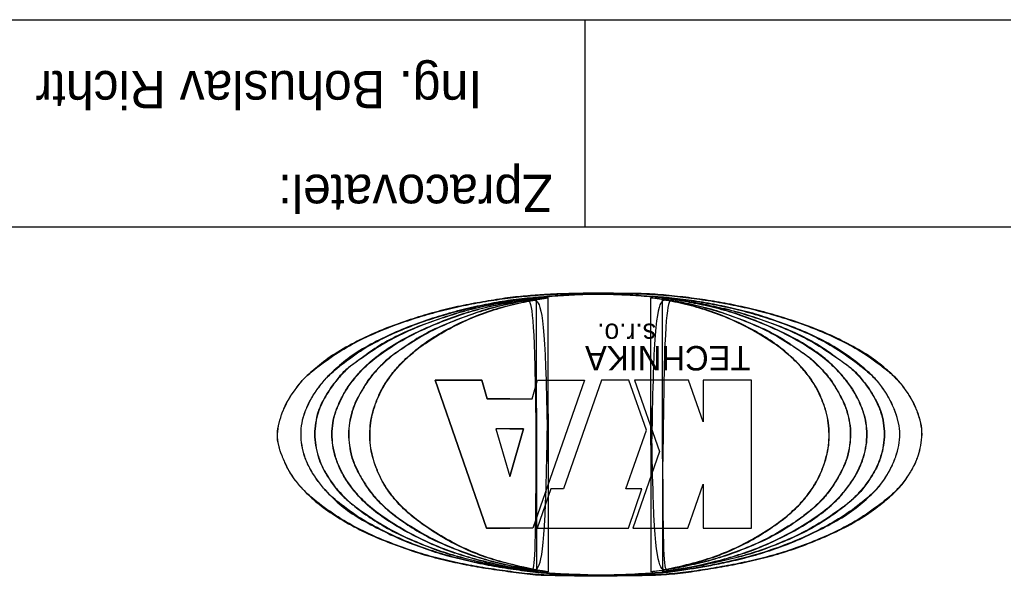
# Model space of a CAD drawing. Extents: x -728452 to -728347, y -1073107 to -1072959.
# Drawn here: x -728436.11 to -728412.4, y -1073023.46 to -1073009.8 of the extents above; entities that cross this region are included whole.
import ezdxf

# ---------------------------------------------------------------- set-up
doc = ezdxf.new("R2010")
doc.units = 0
doc.layers.add('Dočasný_nad_1_rok', color=7, linetype='Continuous')
doc.layers.add('Dočasný_nad_1_rok_PUPFL', color=7, linetype='Continuous')

msp = doc.modelspace()

# ---------------------------------------------------------------- linework, layer by layer
at = {"layer": 'Dočasný_nad_1_rok'}
msp.add_line((-728424.294, -1073022.056), (-728424.851, -1073022.056), dxfattribs=at)
for points in [[(-728424.294, -1073018.942), (-728424.836, -1073018.942), (-728424.968, -1073018.486), (-728426.094, -1073018.487), (-728424.851, -1073022.056), (-728424.294, -1073022.056)], [(-728424.851, -1073022.056), (-728426.094, -1073018.487), (-728424.968, -1073018.486), (-728424.836, -1073018.942), (-728424.294, -1073018.942)], [(-728424.294, -1073018.942), (-728423.753, -1073018.942), (-728423.621, -1073018.486), (-728422.495, -1073018.487), (-728423.738, -1073022.056), (-728424.294, -1073022.056)], [(-728424.294, -1073018.942), (-728423.753, -1073018.942), (-728423.621, -1073018.486), (-728422.495, -1073018.487), (-728423.738, -1073022.056), (-728424.294, -1073022.056)], [(-728421.435, -1073022.056), (-728421.107, -1073021.113), (-728421.495, -1073021.113), (-728421.001, -1073019.693), (-728421.421, -1073018.486), (-728422.085, -1073018.486), (-728423, -1073021.113), (-728423.302, -1073021.113), (-728423.63, -1073022.056), (-728421.435, -1073022.056)], [(-728421.435, -1073022.056), (-728421.107, -1073021.113), (-728421.495, -1073021.113), (-728421.001, -1073019.693), (-728421.421, -1073018.486), (-728422.085, -1073018.486), (-728423, -1073021.113), (-728423.302, -1073021.113), (-728423.63, -1073022.056), (-728421.435, -1073022.056)], [(-728418.466, -1073022.056), (-728418.466, -1073018.486), (-728419.635, -1073018.486), (-728419.635, -1073019.492), (-728419.985, -1073018.486), (-728421.285, -1073018.486), (-728420.685, -1073020.209), (-728421.328, -1073022.056), (-728420.003, -1073022.056), (-728419.635, -1073020.998), (-728419.635, -1073022.056), (-728418.466, -1073022.056)], [(-728418.466, -1073022.056), (-728418.466, -1073018.486), (-728419.635, -1073018.486), (-728419.635, -1073019.492), (-728419.985, -1073018.486), (-728421.285, -1073018.486), (-728420.685, -1073020.209), (-728421.328, -1073022.056), (-728420.003, -1073022.056), (-728419.635, -1073020.998), (-728419.635, -1073022.056), (-728418.466, -1073022.056)], [(-728424.294, -1073019.665), (-728424.626, -1073019.665), (-728424.294, -1073020.813)], [(-728424.294, -1073019.665), (-728424.626, -1073019.665), (-728424.294, -1073020.813)], [(-728424.294, -1073019.665), (-728423.962, -1073019.665), (-728424.294, -1073020.813)], [(-728424.294, -1073020.813), (-728423.962, -1073019.665), (-728424.294, -1073019.665)]]:
    msp.add_lwpolyline(points, dxfattribs=at)
for points in [[(-728423.358, -1073016.421), (-728423.485, -1073016.428), (-728423.79, -1073016.45), (-728424.276, -1073016.491), (-728424.81, -1073016.579), (-728425.348, -1073016.67), (-728425.885, -1073016.792), (-728426.423, -1073016.94), (-728426.96, -1073017.117), (-728427.498, -1073017.323), (-728428.038, -1073017.576), (-728428.59, -1073017.889), (-728428.983, -1073018.211), (-728429.3, -1073018.476), (-728429.469, -1073018.716), (-728429.656, -1073018.975), (-728429.776, -1073019.251), (-728429.866, -1073019.519), (-728429.918, -1073019.791), (-728429.881, -1073020.068), (-728429.779, -1073020.334), (-728429.665, -1073020.608), (-728429.497, -1073020.882), (-728429.302, -1073021.107), (-728429, -1073021.403), (-728428.589, -1073021.714), (-728428.042, -1073022.034), (-728427.504, -1073022.292), (-728426.96, -1073022.493), (-728426.428, -1073022.686), (-728425.885, -1073022.82), (-728425.349, -1073022.944), (-728424.808, -1073023.035), (-728424.271, -1073023.105), (-728423.738, -1073023.188), (-728423.202, -1073023.194), (-728422.666, -1073023.205), (-728422.309, -1073023.208), (-728422.13, -1073023.209)], [(-728422.13, -1073023.209), (-728421.524, -1073023.201), (-728421.057, -1073023.194), (-728420.521, -1073023.172), (-728419.985, -1073023.116), (-728419.45, -1073023.032), (-728418.912, -1073022.939), (-728418.377, -1073022.824), (-728417.841, -1073022.684), (-728417.303, -1073022.509), (-728416.767, -1073022.295), (-728416.234, -1073022.049), (-728415.697, -1073021.731), (-728415.161, -1073021.327), (-728414.953, -1073021.133), (-728414.734, -1073020.864), (-728414.572, -1073020.597), (-728414.451, -1073020.328), (-728414.386, -1073020.061), (-728414.356, -1073019.793), (-728414.384, -1073019.529), (-728414.465, -1073019.258), (-728414.586, -1073018.988), (-728414.754, -1073018.722), (-728414.97, -1073018.453), (-728415.161, -1073018.274), (-728415.697, -1073017.868), (-728416.233, -1073017.565), (-728416.763, -1073017.318), (-728417.305, -1073017.113), (-728417.843, -1073016.939), (-728418.376, -1073016.793), (-728418.909, -1073016.675), (-728419.447, -1073016.577), (-728419.985, -1073016.501), (-728420.523, -1073016.442), (-728421.054, -1073016.406), (-728421.594, -1073016.4), (-728422.13, -1073016.391), (-728422.666, -1073016.4), (-728423.203, -1073016.414), (-728423.739, -1073016.447), (-728424.272, -1073016.498), (-728424.81, -1073016.579), (-728425.345, -1073016.674), (-728425.881, -1073016.795), (-728426.419, -1073016.944), (-728426.955, -1073017.12), (-728427.491, -1073017.328), (-728428.024, -1073017.577), (-728428.564, -1073017.893), (-728429.103, -1073018.311), (-728429.263, -1073018.454), (-728429.473, -1073018.72), (-728429.65, -1073018.987), (-728429.774, -1073019.257), (-728429.861, -1073019.524), (-728429.904, -1073019.793), (-728429.872, -1073020.06), (-728429.78, -1073020.329), (-728429.659, -1073020.603), (-728429.499, -1073020.864), (-728429.272, -1073021.133), (-728429.106, -1073021.296), (-728428.565, -1073021.715), (-728428.029, -1073022.032), (-728427.496, -1073022.286), (-728426.958, -1073022.493), (-728426.419, -1073022.678), (-728425.886, -1073022.818), (-728425.346, -1073022.939), (-728424.807, -1073023.031), (-728424.268, -1073023.107), (-728423.737, -1073023.175), (-728423.202, -1073023.194), (-728422.667, -1073023.204), (-728422.13, -1073023.209), (-728422.13, -1073023.209), (-728422.13, -1073023.209)], [(-728422.13, -1073023.194), (-728422.309, -1073023.187), (-728422.666, -1073023.173), (-728423.204, -1073023.167), (-728423.739, -1073023.109), (-728424.275, -1073023.04), (-728424.813, -1073022.951), (-728425.348, -1073022.833), (-728425.889, -1073022.704), (-728426.424, -1073022.522), (-728426.965, -1073022.316), (-728427.499, -1073022.051), (-728428.056, -1073021.752), (-728428.468, -1073021.424), (-728428.773, -1073021.118), (-728428.965, -1073020.876), (-728429.13, -1073020.605), (-728429.252, -1073020.336), (-728429.316, -1073020.062), (-728429.34, -1073019.792), (-728429.319, -1073019.519), (-728429.238, -1073019.25), (-728429.118, -1073018.979), (-728428.946, -1073018.711), (-728428.764, -1073018.473), (-728428.455, -1073018.183), (-728428.056, -1073017.853), (-728427.503, -1073017.541), (-728426.962, -1073017.291), (-728426.424, -1073017.082), (-728425.885, -1073016.913), (-728425.349, -1073016.764), (-728424.811, -1073016.653), (-728424.275, -1073016.555), (-728423.737, -1073016.502), (-728423.202, -1073016.456), (-728422.666, -1073016.422), (-728422.13, -1073016.404), (-728421.593, -1073016.424), (-728421.057, -1073016.463), (-728420.52, -1073016.492), (-728419.983, -1073016.556), (-728419.446, -1073016.643), (-728418.909, -1073016.756), (-728418.37, -1073016.889), (-728417.837, -1073017.074), (-728417.295, -1073017.268), (-728416.752, -1073017.514), (-728416.213, -1073017.841), (-728415.79, -1073018.162), (-728415.467, -1073018.457), (-728415.274, -1073018.709), (-728415.114, -1073018.981), (-728414.994, -1073019.251), (-728414.919, -1073019.521), (-728414.872, -1073019.792), (-728414.913, -1073020.064), (-728414.983, -1073020.335), (-728415.096, -1073020.606), (-728415.255, -1073020.875), (-728415.448, -1073021.139), (-728415.783, -1073021.437), (-728416.206, -1073021.773), (-728416.761, -1073022.069), (-728417.295, -1073022.329), (-728417.834, -1073022.538), (-728418.372, -1073022.71), (-728418.91, -1073022.848), (-728419.368, -1073022.939), (-728419.726, -1073023.004), (-728420.083, -1073023.062), (-728420.52, -1073023.126), (-728421.057, -1073023.16), (-728421.593, -1073023.182), (-728421.951, -1073023.19), (-728422.13, -1073023.194)], [(-728422.13, -1073023.194), (-728421.593, -1073023.18), (-728421.057, -1073023.158), (-728420.522, -1073023.119), (-728419.986, -1073023.046), (-728419.744, -1073023.006), (-728419.45, -1073022.953), (-728418.913, -1073022.843), (-728418.377, -1073022.706), (-728417.84, -1073022.534), (-728417.304, -1073022.324), (-728416.767, -1073022.068), (-728416.234, -1073021.768), (-728415.698, -1073021.358), (-728415.459, -1073021.133), (-728415.254, -1073020.864), (-728415.1, -1073020.598), (-728414.987, -1073020.328), (-728414.917, -1073020.061), (-728414.886, -1073019.792), (-728414.923, -1073019.525), (-728414.999, -1073019.258), (-728415.116, -1073018.989), (-728415.274, -1073018.721), (-728415.484, -1073018.452), (-728415.698, -1073018.25), (-728416.233, -1073017.841), (-728416.767, -1073017.52), (-728417.303, -1073017.273), (-728417.839, -1073017.074), (-728418.376, -1073016.896), (-728418.912, -1073016.759), (-728419.448, -1073016.647), (-728419.985, -1073016.559), (-728420.521, -1073016.498), (-728421.057, -1073016.461), (-728421.594, -1073016.427), (-728422.13, -1073016.41), (-728422.665, -1073016.424), (-728423.203, -1073016.458), (-728423.736, -1073016.503), (-728424.272, -1073016.562), (-728424.809, -1073016.655), (-728425.345, -1073016.77), (-728425.881, -1073016.915), (-728426.419, -1073017.087), (-728426.955, -1073017.294), (-728427.49, -1073017.544), (-728428.028, -1073017.857), (-728428.563, -1073018.286), (-728428.735, -1073018.453), (-728428.948, -1073018.722), (-728429.114, -1073018.988), (-728429.234, -1073019.257), (-728429.31, -1073019.524), (-728429.333, -1073019.79), (-728429.31, -1073020.06), (-728429.246, -1073020.327), (-728429.128, -1073020.596), (-728428.965, -1073020.864), (-728428.752, -1073021.133), (-728428.564, -1073021.324), (-728428.028, -1073021.747), (-728427.491, -1073022.052), (-728426.955, -1073022.31), (-728426.419, -1073022.52), (-728425.882, -1073022.697), (-728425.346, -1073022.832), (-728424.81, -1073022.947), (-728424.273, -1073023.037), (-728423.737, -1073023.107), (-728423.203, -1073023.159), (-728422.667, -1073023.175), (-728422.13, -1073023.194), (-728422.13, -1073023.194), (-728422.13, -1073023.194)], [(-728423.648, -1073016.51), (-728423.751, -1073016.519), (-728423.961, -1073016.536), (-728424.35, -1073016.596), (-728424.815, -1073016.691), (-728425.357, -1073016.807), (-728425.891, -1073016.978), (-728426.43, -1073017.164), (-728426.97, -1073017.397), (-728427.517, -1073017.69), (-728427.898, -1073017.991), (-728428.237, -1073018.214), (-728428.437, -1073018.44), (-728428.642, -1073018.713), (-728428.801, -1073018.982), (-728428.924, -1073019.247), (-728428.979, -1073019.522), (-728429.009, -1073019.792), (-728428.98, -1073020.063), (-728428.918, -1073020.335), (-728428.813, -1073020.61), (-728428.647, -1073020.872), (-728428.455, -1073021.156), (-728428.236, -1073021.366), (-728427.915, -1073021.628), (-728427.512, -1073021.91), (-728426.969, -1073022.216), (-728426.426, -1073022.444), (-728425.891, -1073022.648), (-728425.351, -1073022.793), (-728424.81, -1073022.914), (-728424.275, -1073023.021), (-728423.887, -1073023.09), (-728423.678, -1073023.102), (-728423.65, -1073023.104)], [(-728423.648, -1073016.51), (-728423.956, -1073016.539), (-728424.277, -1073016.586), (-728424.813, -1073016.691), (-728425.352, -1073016.815), (-728425.889, -1073016.979), (-728426.423, -1073017.168), (-728426.956, -1073017.4), (-728427.494, -1073017.698), (-728428.033, -1073018.079), (-728428.178, -1073018.181), (-728428.441, -1073018.452), (-728428.644, -1073018.726), (-728428.799, -1073018.989), (-728428.914, -1073019.254), (-728428.975, -1073019.526), (-728428.999, -1073019.794), (-728428.975, -1073020.057), (-728428.912, -1073020.33), (-728428.807, -1073020.6), (-728428.649, -1073020.865), (-728428.457, -1073021.133), (-728428.184, -1073021.406), (-728428.037, -1073021.527), (-728427.494, -1073021.909), (-728426.953, -1073022.211), (-728426.418, -1073022.443), (-728425.89, -1073022.638), (-728425.342, -1073022.791), (-728424.811, -1073022.912), (-728424.272, -1073023.02), (-728423.734, -1073023.099), (-728423.65, -1073023.104), (-728423.648, -1073016.51), (-728423.65, -1073023.104)], [(-728423.65, -1073023.104), (-728423.843, -1073023.075), (-728424.232, -1073023.017), (-728424.8, -1073022.9), (-728425.353, -1073022.748), (-728425.893, -1073022.569), (-728426.429, -1073022.333), (-728426.97, -1073022.049), (-728427.444, -1073021.74), (-728427.816, -1073021.429), (-728428.064, -1073021.143), (-728428.258, -1073020.877), (-728428.403, -1073020.606), (-728428.506, -1073020.335), (-728428.568, -1073020.063), (-728428.586, -1073019.791), (-728428.567, -1073019.521), (-728428.499, -1073019.25), (-728428.383, -1073018.983), (-728428.242, -1073018.708), (-728428.04, -1073018.443), (-728427.796, -1073018.165), (-728427.436, -1073017.855), (-728426.97, -1073017.551), (-728426.426, -1073017.277), (-728425.887, -1073017.048), (-728425.352, -1073016.857), (-728424.814, -1073016.713), (-728424.328, -1073016.614), (-728423.939, -1073016.55), (-728423.73, -1073016.521), (-728423.648, -1073016.51)], [(-728423.65, -1073023.104), (-728424.229, -1073023.012), (-728424.81, -1073022.891), (-728425.349, -1073022.744), (-728425.887, -1073022.562), (-728426.418, -1073022.331), (-728426.954, -1073022.047), (-728427.491, -1073021.691), (-728427.828, -1073021.402), (-728428.067, -1073021.131), (-728428.256, -1073020.866), (-728428.398, -1073020.601), (-728428.501, -1073020.329), (-728428.562, -1073020.058), (-728428.58, -1073019.793), (-728428.559, -1073019.523), (-728428.493, -1073019.257), (-728428.383, -1073018.99), (-728428.238, -1073018.719), (-728428.044, -1073018.454), (-728427.804, -1073018.186), (-728427.486, -1073017.908), (-728426.955, -1073017.556), (-728426.416, -1073017.28), (-728425.881, -1073017.052), (-728425.345, -1073016.863), (-728424.811, -1073016.718), (-728424.274, -1073016.607), (-728423.893, -1073016.544), (-728423.648, -1073016.51), (-728423.65, -1073023.104), (-728423.648, -1073016.51)], [(-728423.369, -1073016.502), (-728423.492, -1073016.512), (-728423.797, -1073016.539), (-728424.276, -1073016.641), (-728424.817, -1073016.763), (-728425.35, -1073016.948), (-728425.891, -1073017.156), (-728426.44, -1073017.416), (-728426.844, -1073017.702), (-728427.203, -1073017.939), (-728427.44, -1073018.174), (-728427.683, -1073018.436), (-728427.849, -1073018.718), (-728428.003, -1073018.98), (-728428.106, -1073019.25), (-728428.163, -1073019.52), (-728428.193, -1073019.791), (-728428.16, -1073020.062), (-728428.118, -1073020.335), (-728428.007, -1073020.604), (-728427.864, -1073020.871), (-728427.69, -1073021.146), (-728427.463, -1073021.42), (-728427.207, -1073021.648), (-728426.858, -1073021.911), (-728426.436, -1073022.188), (-728425.893, -1073022.454), (-728425.354, -1073022.664), (-728424.818, -1073022.84), (-728424.278, -1073022.963), (-728423.797, -1073023.062), (-728423.492, -1073023.097), (-728423.369, -1073023.111)], [(-728423.369, -1073016.502), (-728423.737, -1073016.54), (-728424.276, -1073016.642), (-728424.807, -1073016.771), (-728425.346, -1073016.95), (-728425.884, -1073017.16), (-728426.417, -1073017.423), (-728426.954, -1073017.774), (-728427.157, -1073017.916), (-728427.449, -1073018.186), (-728427.68, -1073018.452), (-728427.851, -1073018.721), (-728427.998, -1073018.989), (-728428.101, -1073019.257), (-728428.159, -1073019.52), (-728428.182, -1073019.792), (-728428.159, -1073020.062), (-728428.109, -1073020.328), (-728428.006, -1073020.594), (-728427.862, -1073020.867), (-728427.691, -1073021.133), (-728427.467, -1073021.402), (-728427.173, -1073021.67), (-728426.952, -1073021.838), (-728426.418, -1073022.183), (-728425.884, -1073022.449), (-728425.345, -1073022.662), (-728424.813, -1073022.833), (-728424.277, -1073022.961), (-728423.737, -1073023.065), (-728423.369, -1073023.111), (-728423.369, -1073016.502), (-728423.369, -1073023.111)], [(-728423.369, -1073023.111), (-728423.492, -1073023.093), (-728423.796, -1073023.049), (-728424.276, -1073022.931), (-728424.819, -1073022.787), (-728425.36, -1073022.576), (-728425.899, -1073022.298), (-728426.371, -1073021.989), (-728426.758, -1073021.692), (-728427.029, -1073021.412), (-728427.242, -1073021.145), (-728427.403, -1073020.873), (-728427.519, -1073020.602), (-728427.606, -1073020.332), (-728427.662, -1073020.063), (-728427.67, -1073019.792), (-728427.655, -1073019.522), (-728427.603, -1073019.251), (-728427.507, -1073018.985), (-728427.389, -1073018.711), (-728427.219, -1073018.444), (-728427.006, -1073018.173), (-728426.736, -1073017.907), (-728426.368, -1073017.6), (-728425.899, -1073017.308), (-728425.358, -1073017.04), (-728424.82, -1073016.821), (-728424.278, -1073016.67), (-728423.794, -1073016.57), (-728423.492, -1073016.522), (-728423.369, -1073016.502)], [(-728423.369, -1073023.111), (-728423.737, -1073023.053), (-728424.273, -1073022.93), (-728424.811, -1073022.778), (-728425.347, -1073022.57), (-728425.883, -1073022.295), (-728426.419, -1073021.947), (-728426.771, -1073021.667), (-728427.031, -1073021.401), (-728427.242, -1073021.132), (-728427.4, -1073020.866), (-728427.517, -1073020.597), (-728427.602, -1073020.329), (-728427.655, -1073020.06), (-728427.667, -1073019.794), (-728427.649, -1073019.525), (-728427.596, -1073019.256), (-728427.506, -1073018.99), (-728427.385, -1073018.722), (-728427.219, -1073018.453), (-728427.011, -1073018.19), (-728426.741, -1073017.919), (-728426.419, -1073017.653), (-728425.884, -1073017.311), (-728425.348, -1073017.043), (-728424.812, -1073016.83), (-728424.271, -1073016.675), (-728423.738, -1073016.563), (-728423.369, -1073016.502), (-728423.369, -1073023.111), (-728423.369, -1073016.502)], [(-728422.13, -1073023.209), (-728421.928, -1073023.206), (-728421.57, -1073023.2), (-728421.034, -1073023.196), (-728420.52, -1073023.179), (-728419.983, -1073023.121), (-728419.449, -1073023.032), (-728418.911, -1073022.943), (-728418.374, -1073022.827), (-728417.835, -1073022.688), (-728417.297, -1073022.513), (-728416.763, -1073022.297), (-728416.218, -1073022.054), (-728415.678, -1073021.732), (-728415.255, -1073021.416), (-728414.933, -1073021.124), (-728414.735, -1073020.877), (-728414.57, -1073020.605), (-728414.442, -1073020.338), (-728414.384, -1073020.063), (-728414.344, -1073019.795), (-728414.376, -1073019.521), (-728414.462, -1073019.252), (-728414.581, -1073018.978), (-728414.756, -1073018.712), (-728414.944, -1073018.467), (-728415.262, -1073018.181), (-728415.672, -1073017.863), (-728416.221, -1073017.564), (-728416.758, -1073017.311), (-728417.299, -1073017.111), (-728417.837, -1073016.936), (-728418.372, -1073016.788), (-728418.909, -1073016.672), (-728419.445, -1073016.573), (-728419.984, -1073016.498), (-728420.52, -1073016.44), (-728421.056, -1073016.397), (-728421.592, -1073016.404), (-728422.13, -1073016.385), (-728422.666, -1073016.401), (-728423.076, -1073016.407), (-728423.307, -1073016.418), (-728423.358, -1073016.421)], [(-728420.89, -1073016.502), (-728420.767, -1073016.512), (-728420.462, -1073016.539), (-728419.983, -1073016.641), (-728419.442, -1073016.763), (-728418.909, -1073016.948), (-728418.368, -1073017.156), (-728417.819, -1073017.416), (-728417.415, -1073017.702), (-728417.056, -1073017.939), (-728416.819, -1073018.174), (-728416.576, -1073018.436), (-728416.41, -1073018.718), (-728416.257, -1073018.98), (-728416.153, -1073019.25), (-728416.096, -1073019.52), (-728416.066, -1073019.791), (-728416.099, -1073020.062), (-728416.141, -1073020.335), (-728416.252, -1073020.604), (-728416.395, -1073020.871), (-728416.569, -1073021.146), (-728416.796, -1073021.42), (-728417.052, -1073021.648), (-728417.401, -1073021.911), (-728417.823, -1073022.188), (-728418.367, -1073022.454), (-728418.906, -1073022.664), (-728419.441, -1073022.84), (-728419.981, -1073022.963), (-728420.462, -1073023.062), (-728420.767, -1073023.097), (-728420.891, -1073023.111)], [(-728420.891, -1073023.111), (-728420.767, -1073023.093), (-728420.463, -1073023.049), (-728419.983, -1073022.931), (-728419.44, -1073022.787), (-728418.9, -1073022.576), (-728418.36, -1073022.298), (-728417.888, -1073021.989), (-728417.501, -1073021.692), (-728417.231, -1073021.412), (-728417.018, -1073021.145), (-728416.856, -1073020.873), (-728416.74, -1073020.602), (-728416.653, -1073020.332), (-728416.597, -1073020.063), (-728416.589, -1073019.792), (-728416.604, -1073019.522), (-728416.657, -1073019.251), (-728416.752, -1073018.985), (-728416.87, -1073018.711), (-728417.04, -1073018.444), (-728417.253, -1073018.173), (-728417.523, -1073017.907), (-728417.891, -1073017.6), (-728418.36, -1073017.308), (-728418.902, -1073017.04), (-728419.439, -1073016.821), (-728419.981, -1073016.67), (-728420.465, -1073016.57), (-728420.767, -1073016.522), (-728420.89, -1073016.502)], [(-728420.89, -1073016.502), (-728420.522, -1073016.54), (-728419.983, -1073016.642), (-728419.452, -1073016.771), (-728418.913, -1073016.95), (-728418.376, -1073017.16), (-728417.842, -1073017.423), (-728417.305, -1073017.774), (-728417.102, -1073017.916), (-728416.811, -1073018.186), (-728416.579, -1073018.452), (-728416.408, -1073018.721), (-728416.261, -1073018.989), (-728416.158, -1073019.257), (-728416.101, -1073019.52), (-728416.077, -1073019.792), (-728416.1, -1073020.062), (-728416.15, -1073020.328), (-728416.253, -1073020.594), (-728416.397, -1073020.867), (-728416.568, -1073021.133), (-728416.792, -1073021.402), (-728417.086, -1073021.67), (-728417.307, -1073021.838), (-728417.841, -1073022.183), (-728418.375, -1073022.449), (-728418.914, -1073022.662), (-728419.446, -1073022.833), (-728419.982, -1073022.961), (-728420.522, -1073023.065), (-728420.891, -1073023.111), (-728420.89, -1073016.502), (-728420.891, -1073023.111)], [(-728420.891, -1073023.111), (-728420.522, -1073023.053), (-728419.986, -1073022.93), (-728419.448, -1073022.778), (-728418.913, -1073022.57), (-728418.376, -1073022.295), (-728417.841, -1073021.947), (-728417.489, -1073021.667), (-728417.228, -1073021.401), (-728417.018, -1073021.132), (-728416.86, -1073020.866), (-728416.743, -1073020.597), (-728416.657, -1073020.329), (-728416.604, -1073020.06), (-728416.593, -1073019.794), (-728416.61, -1073019.525), (-728416.663, -1073019.256), (-728416.754, -1073018.99), (-728416.874, -1073018.722), (-728417.041, -1073018.453), (-728417.248, -1073018.19), (-728417.518, -1073017.919), (-728417.84, -1073017.653), (-728418.375, -1073017.311), (-728418.911, -1073017.043), (-728419.447, -1073016.83), (-728419.988, -1073016.675), (-728420.522, -1073016.563), (-728420.89, -1073016.502), (-728420.891, -1073023.111), (-728420.89, -1073016.502)], [(-728420.609, -1073023.104), (-728420.416, -1073023.075), (-728420.027, -1073023.017), (-728419.459, -1073022.9), (-728418.906, -1073022.748), (-728418.366, -1073022.569), (-728417.83, -1073022.333), (-728417.289, -1073022.049), (-728416.815, -1073021.74), (-728416.443, -1073021.429), (-728416.196, -1073021.143), (-728416.001, -1073020.877), (-728415.857, -1073020.606), (-728415.753, -1073020.335), (-728415.691, -1073020.063), (-728415.673, -1073019.791), (-728415.692, -1073019.521), (-728415.76, -1073019.25), (-728415.876, -1073018.983), (-728416.017, -1073018.708), (-728416.219, -1073018.443), (-728416.464, -1073018.165), (-728416.823, -1073017.855), (-728417.289, -1073017.551), (-728417.833, -1073017.277), (-728418.372, -1073017.048), (-728418.907, -1073016.857), (-728419.445, -1073016.713), (-728419.932, -1073016.614), (-728420.32, -1073016.55), (-728420.529, -1073016.521), (-728420.611, -1073016.51)], [(-728420.611, -1073016.51), (-728420.508, -1073016.519), (-728420.298, -1073016.536), (-728419.909, -1073016.596), (-728419.444, -1073016.691), (-728418.902, -1073016.807), (-728418.368, -1073016.978), (-728417.829, -1073017.164), (-728417.289, -1073017.397), (-728416.742, -1073017.69), (-728416.361, -1073017.991), (-728416.023, -1073018.214), (-728415.822, -1073018.44), (-728415.617, -1073018.713), (-728415.459, -1073018.982), (-728415.335, -1073019.247), (-728415.28, -1073019.522), (-728415.25, -1073019.792), (-728415.279, -1073020.063), (-728415.341, -1073020.335), (-728415.446, -1073020.61), (-728415.613, -1073020.872), (-728415.804, -1073021.156), (-728416.023, -1073021.366), (-728416.344, -1073021.628), (-728416.747, -1073021.91), (-728417.29, -1073022.216), (-728417.834, -1073022.444), (-728418.368, -1073022.648), (-728418.909, -1073022.793), (-728419.45, -1073022.914), (-728419.985, -1073023.021), (-728420.372, -1073023.09), (-728420.581, -1073023.102), (-728420.609, -1073023.104)], [(-728420.611, -1073016.51), (-728420.303, -1073016.539), (-728419.983, -1073016.586), (-728419.446, -1073016.691), (-728418.908, -1073016.815), (-728418.37, -1073016.979), (-728417.836, -1073017.168), (-728417.303, -1073017.4), (-728416.765, -1073017.698), (-728416.226, -1073018.079), (-728416.082, -1073018.181), (-728415.819, -1073018.452), (-728415.615, -1073018.726), (-728415.46, -1073018.989), (-728415.345, -1073019.254), (-728415.284, -1073019.526), (-728415.26, -1073019.794), (-728415.284, -1073020.057), (-728415.347, -1073020.33), (-728415.452, -1073020.6), (-728415.61, -1073020.865), (-728415.802, -1073021.133), (-728416.075, -1073021.406), (-728416.222, -1073021.527), (-728416.765, -1073021.909), (-728417.307, -1073022.211), (-728417.841, -1073022.443), (-728418.369, -1073022.638), (-728418.917, -1073022.791), (-728419.448, -1073022.912), (-728419.987, -1073023.02), (-728420.525, -1073023.099), (-728420.609, -1073023.104), (-728420.611, -1073016.51), (-728420.609, -1073023.104)], [(-728420.609, -1073023.104), (-728420.03, -1073023.012), (-728419.45, -1073022.891), (-728418.911, -1073022.744), (-728418.373, -1073022.562), (-728417.842, -1073022.331), (-728417.305, -1073022.047), (-728416.768, -1073021.691), (-728416.431, -1073021.402), (-728416.192, -1073021.131), (-728416.003, -1073020.866), (-728415.861, -1073020.601), (-728415.758, -1073020.329), (-728415.698, -1073020.058), (-728415.679, -1073019.793), (-728415.7, -1073019.523), (-728415.766, -1073019.257), (-728415.876, -1073018.99), (-728416.021, -1073018.719), (-728416.215, -1073018.454), (-728416.455, -1073018.186), (-728416.773, -1073017.908), (-728417.304, -1073017.556), (-728417.843, -1073017.28), (-728418.378, -1073017.052), (-728418.914, -1073016.863), (-728419.448, -1073016.718), (-728419.985, -1073016.607), (-728420.366, -1073016.544), (-728420.611, -1073016.51), (-728420.609, -1073023.104), (-728420.611, -1073016.51)]]:
    msp.add_open_spline(points, degree=3, dxfattribs=at)
at = {"layer": 'Dočasný_nad_1_rok_PUPFL'}
for p, q in [((-728422.485, -1073009.8), (-728422.485, -1073014.8)), ((-728357.31, -1073014.8), (-728442.31, -1073014.8))]:
    msp.add_line(p, q, dxfattribs=at)
msp.add_lwpolyline([(-728357.31, -1073034.8), (-728442.31, -1073034.8), (-728442.31, -1073009.8), (-728357.31, -1073009.8)], close=True, dxfattribs=at)

# ---------------------------------------------------------------- texts
at = {"layer": 'Dočasný_nad_1_rok'}
for s, height, p in [('s.r.o.', 0.4772, (-728420.769, -1073017.127)), ('TECHNIKA', 0.5898, (-728418.491, -1073017.666))]:
    msp.add_text(s, height=height, rotation=180, dxfattribs=at).set_placement(p)
at = {"layer": 'Dočasný_nad_1_rok_PUPFL'}
for s, p in [('Ing. Bohuslav Richtr', (-728424.958, -1073011.037)), ('Zpracovatel:', (-728423.258, -1073013.537))]:
    msp.add_text(s, height=0.9, rotation=180, dxfattribs=at).set_placement(p)

doc.saveas('drawing.dxf')
